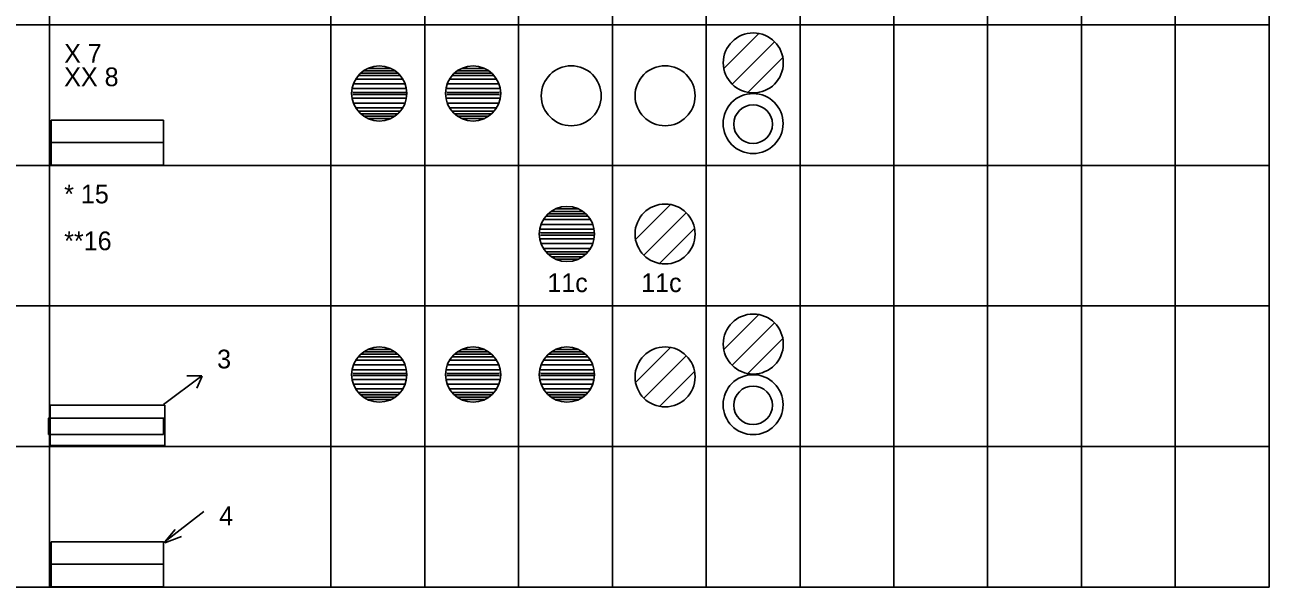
# Model space of a CAD drawing. Extents: x -28 to 822, y 61 to 665.
# Drawn here: x 458 to 590.6, y 111.7 to 171.7 of the extents above; entities that cross this region are included whole.
import ezdxf

# ---------------------------------------------------------------- set-up
doc = ezdxf.new("R2010")
doc.units = 0
doc.layers.add('KOLEJIŠTĚ', color=7, linetype='Continuous')
doc.layers.add('nové', color=7, linetype='Continuous')

# ---------------------------------------------------------------- blocks, each defined once
blk = doc.blocks.new('ZT18')
for p, q in [((10, 6), (0, 6)), ((0, 6), (0, 2)), ((10, 2), (10, 6)), ((0, 2), (10, 2))]:
    blk.add_line(p, q)
blk.add_lwpolyline([(0, 4), (0, 4), (10, 4)])
blk = doc.blocks.new('ZT95')
for p, q in [((2.793, 4.073), (0.927, 2.207)), ((3.631, 3.631), (1.369, 1.369)), ((4.073, 2.793), (2.207, 0.927))]:
    blk.add_line(p, q)
blk.add_circle((2.5, 2.5), 1.6)
blk = doc.blocks.new('HR6')
for p, q in [((-0.95, 2.09), (0.95, 2.09)), ((-1.96, 1.2), (1.96, 1.2)), ((-1.75, 1.49), (1.75, 1.49)), ((-1.56, 1.69), (1.56, 1.69)), ((-1.3, 1.89), (1.3, 1.89)), ((-2.26, 0.4), (2.26, 0.4)), ((-2.2, 0.09), (2.2, 0.09)), ((-2.16, 0.8), (2.16, 0.8)), ((-2.26, -0.4), (2.26, -0.4)), ((-2.2, -0.09), (2.2, -0.09)), ((-2.16, -0.8), (2.16, -0.8)), ((-1.96, -1.2), (1.96, -1.2)), ((-1.75, -1.49), (1.75, -1.49)), ((-1.56, -1.69), (1.56, -1.69)), ((-1.3, -1.89), (1.3, -1.89)), ((-0.95, -2.09), (0.95, -2.09))]:
    blk.add_line(p, q)
for start, end in [(0, 180), (180, 0)]:
    blk.add_arc((0, 0), 2.3, start, end)
blk = doc.blocks.new('ZT94')
at = {"xscale": 0.6400000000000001, "yscale": 0.6400000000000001}
blk.add_blockref('HR6', (2.5, 2.5), dxfattribs=at)

msp = doc.modelspace()

# ---------------------------------------------------------------- linework, layer by layer
for p, q in [((460.62, 381.74), (460.62, 111.74)), ((460.62, 381.74), (460.62, 111.74)), ((490.62, 381.74), (490.62, 111.74)), ((500.62, 381.74), (500.62, 111.74)), ((510.62, 381.74), (510.62, 111.74)), ((520.62, 381.74), (520.62, 111.74)), ((530.62, 381.74), (530.62, 111.74)), ((560.62, 381.74), (560.62, 111.74)), ((5.07, 171.74), (540.62, 171.74)), ((348.12, 156.74), (540.62, 156.74)), ((5.07, 141.74), (540.62, 141.74)), ((472.79, 131.24), (476.88, 134.3)), ((476.88, 134.3), (475.27, 134.3)), ((476.89, 134.26), (476.35, 132.96)), ((340.62, 126.74), (540.62, 126.74)), ((472.82, 116.51), (477.08, 119.82)), ((472.91, 116.57), (474.02, 117.9)), ((472.91, 116.46), (474.69, 117.13)), ((5.07, 111.74), (540.62, 111.74))]:
    msp.add_line(p, q)
for points in [[(472.91, 126.84), (460.72, 126.84), (460.72, 131.15), (472.91, 131.15)], [(472.79, 128.03), (460.54, 128.03), (460.54, 129.78), (472.79, 129.78)]]:
    msp.add_lwpolyline(points, close=True)
for centre, radius in [((516.24, 164.17), 3.2), ((526.24, 164.17), 3.2), ((535.62, 161.21), 3.2), ((535.62, 161.14), 2.06), ((535.62, 131.21), 3.2), ((535.62, 131.14), 2.06)]:
    msp.add_circle(centre, radius)
at = {"layer": 'nové'}
for p, q in [((540.62, 381.74), (540.62, 111.74)), ((550.62, 381.74), (550.62, 111.74)), ((570.62, 381.74), (570.62, 111.74)), ((580.62, 381.74), (580.62, 111.74)), ((590.62, 381.74), (590.62, 111.74)), ((540.62, 171.74), (590.62, 171.74)), ((540.62, 156.74), (590.62, 156.74)), ((540.62, 141.74), (590.62, 141.74)), ((540.62, 126.74), (590.62, 126.74)), ((540.62, 111.74), (590.62, 111.74))]:
    msp.add_line(p, q, dxfattribs=at)

# ---------------------------------------------------------------- block references
at = {"layer": 'KOLEJIŠTĚ'}
for name, p, xscale, yscale in [('ZT95', (530.64, 162.68), 2, 2), ('ZT94', (490.78, 159.42), 2, 2), ('ZT94', (500.78, 159.42), 2, 2), ('ZT18', (460.8, 154.38), 1.2000000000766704, 1.2000000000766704), ('ZT95', (521.24, 144.42), 2, 2), ('ZT94', (510.78, 144.42), 2, 2), ('ZT95', (530.64, 132.68), 2, 2), ('ZT94', (490.78, 129.42), 2, 2), ('ZT94', (500.78, 129.42), 2, 2), ('ZT94', (510.78, 129.42), 2, 2), ('ZT95', (521.24, 129.17), 2, 2), ('ZT18', (460.8, 109.38), 1.2000000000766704, 1.2000000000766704)]:
    msp.add_blockref(name, p, dxfattribs=dict(at, xscale=xscale, yscale=yscale))

# ---------------------------------------------------------------- texts
for s, p in [('X', (462.2, 167.69)), ('7', (464.7, 167.69)), ('XX 8', (462.2, 165.19)), ('* 15', (462.2, 152.69)), ('**16', (462.2, 147.69)), ('11c', (513.69, 143.22)), ('11c', (523.69, 143.22)), ('3', (478.5, 135.08)), ('4', (478.72, 118.35))]:
    msp.add_text(s, height=2).set_placement(p)

doc.saveas('drawing.dxf')
